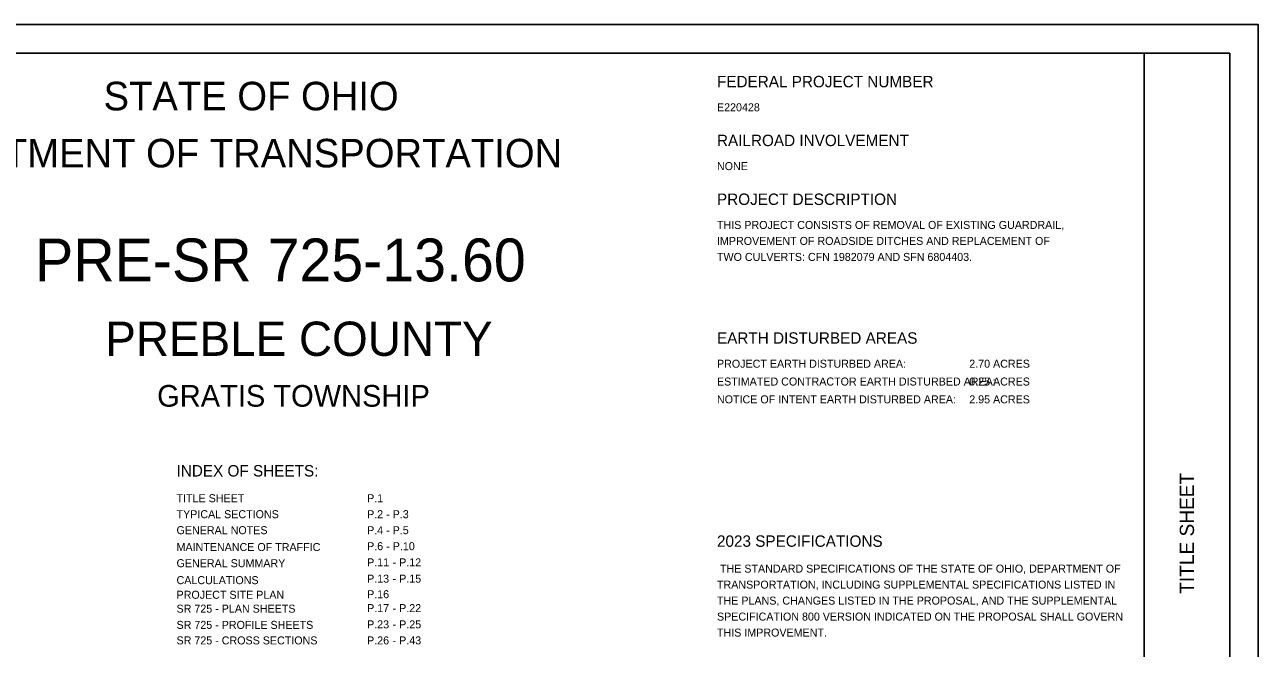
# Model space of a CAD drawing. Extents: x 0 to 34, y 0 to 22.
# Drawn here: x 12.41 to 34, y 11.08 to 22 of the extents above; entities that cross this region are included whole.
import ezdxf

# ---------------------------------------------------------------- set-up
doc = ezdxf.new("R2010")
doc.units = 0
for name, color, linetype in [('SH_Border', 7, 'Continuous'), ('SH_Cut_Line', 7, 'Continuous'), ('SH_Data', 7, 'Continuous'), ('SH_Text', 7, 'Continuous')]:
    doc.layers.add(name, color=color, linetype=linetype)

msp = doc.modelspace()

# ---------------------------------------------------------------- linework, layer by layer
at = {"layer": 'SH_Border'}
msp.add_line((32, 0.5), (32, 21.5), dxfattribs=at)
msp.add_lwpolyline([(1.5, 21.5), (33.5, 21.5), (33.5, 0.5), (1.5, 0.5)], close=True, dxfattribs=at)
at = {"layer": 'SH_Cut_Line'}
msp.add_lwpolyline([(0, 0), (34, 0), (34, 22), (0, 22)], close=True, dxfattribs=at)

# ---------------------------------------------------------------- texts
at = {"layer": 'SH_Data'}
msp.add_text('TITLE SHEET', height=0.25, rotation=90, dxfattribs=at).set_placement((32.875, 12.035))
at = {"layer": 'SH_Text'}
for s, height, p in [('STATE OF OHIO', 0.5, (13.795, 20.5)), ('FEDERAL PROJECT NUMBER', 0.2, (24.528, 20.903)), ('E220428', 0.14, (24.528, 20.483)), ('RAILROAD INVOLVEMENT', 0.2, (24.528, 19.873)), ('DEPARTMENT OF TRANSPORTATION', 0.5, (9.747, 19.5)), ('NONE', 0.14, (24.528, 19.453)), ('PROJECT DESCRIPTION', 0.2, (24.528, 18.843)), ('THIS PROJECT CONSISTS OF REMOVAL OF EXISTING GUARDRAIL,', 0.14, (24.528, 18.423)), ('PRE-SR 725-13.60', 0.75, (12.597, 17.505)), ('IMPROVEMENT OF ROADSIDE DITCHES AND REPLACEMENT OF', 0.14, (24.528, 18.143)), ('TWO CULVERTS: CFN 1982079 AND SFN 6804403.', 0.14, (24.528, 17.863)), ('PREBLE COUNTY', 0.6, (13.825, 16.2)), ('EARTH DISTURBED AREAS', 0.2, (24.528, 16.413)), ('PROJECT EARTH DISTURBED AREA:', 0.14, (24.528, 15.993)), ('2.70 ACRES', 0.14, (28.942, 15.993)), ('ESTIMATED CONTRACTOR EARTH DISTURBED AREA:', 0.14, (24.528, 15.681)), ('0.25 ACRES', 0.14, (28.942, 15.681)), ('GRATIS TOWNSHIP', 0.38, (14.733, 15.31)), ('NOTICE OF INTENT EARTH DISTURBED AREA:', 0.14, (24.528, 15.369)), ('2.95 ACRES', 0.14, (28.942, 15.369)), ('INDEX OF SHEETS:', 0.2, (15.072, 14.088)), ('TITLE SHEET', 0.14, (15.072, 13.638)), ('P.1', 0.14, (18.406, 13.638)), ('TYPICAL SECTIONS', 0.14, (15.072, 13.358)), ('P.2 - P.3', 0.14, (18.406, 13.358)), ('GENERAL NOTES', 0.14, (15.072, 13.078)), ('P.4 - P.5', 0.14, (18.406, 13.078)), ('2023 SPECIFICATIONS', 0.2, (24.528, 12.857)), ('MAINTENANCE OF TRAFFIC', 0.14, (15.072, 12.783)), ('P.6 - ', 0.14, (18.406, 12.798)), ('P.10', 0.14, (18.855, 12.798)), ('GENERAL SUMMARY', 0.14, (15.072, 12.5)), ('P.11', 0.14, (18.406, 12.515)), (' - ', 0.14, (18.799, 12.515)), ('P.12', 0.14, (18.967, 12.515)), (' THE STANDARD SPECIFICATIONS OF THE STATE OF OHIO, DEPARTMENT OF', 0.14, (24.528, 12.405)), ('CALCULATIONS', 0.14, (15.072, 12.203)), ('P.13', 0.14, (18.406, 12.229)), ('P.15', 0.14, (18.967, 12.229)), ('PROJECT SITE PLAN', 0.14, (15.072, 11.947)), ('P.16', 0.14, (18.406, 11.957)), (' - ', 0.14, (18.799, 12.229)), ('TRANSPORTATION, INCLUDING SUPPLEMENTAL SPECIFICATIONS LISTED IN', 0.14, (24.528, 12.125)), ('THE PLANS, CHANGES LISTED IN THE PROPOSAL, AND THE SUPPLEMENTAL', 0.14, (24.528, 11.845)), ('SR 725 - PLAN SHEETS', 0.14, (15.072, 11.704)), ('P.17', 0.14, (18.406, 11.713)), (' - ', 0.14, (18.799, 11.713)), ('P.22', 0.14, (18.967, 11.713)), ('SPECIFICATION 800 VERSION INDICATED ON THE PROPOSAL SHALL GOVERN', 0.14, (24.528, 11.565)), ('SR 725 - PROFILE SHEETS', 0.14, (15.072, 11.42)), ('P.23', 0.14, (18.406, 11.429)), (' - ', 0.14, (18.799, 11.429)), ('P.25', 0.14, (18.967, 11.429)), ('SR 725 - CROSS SECTIONS', 0.14, (15.072, 11.148)), ('P.26', 0.14, (18.406, 11.148)), ('P.43', 0.14, (18.967, 11.148)), ('THIS IMPROVEMENT.', 0.14, (24.528, 11.285)), (' - ', 0.14, (18.799, 11.148))]:
    msp.add_text(s, height=height, dxfattribs=at).set_placement(p)

doc.saveas('drawing.dxf')
